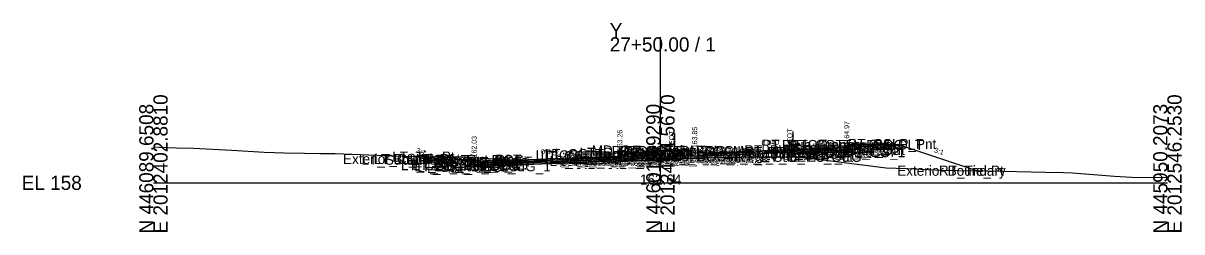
# Model space of a CAD drawing. Extents: x -26 to 3203, y -10 to 9532.
# Drawn here: x 1974.3 to 2202.8, y 1490.3 to 1531.6 of the extents above; entities that cross this region are included whole.
import ezdxf

# ---------------------------------------------------------------- set-up
doc = ezdxf.new("R2010")
doc.units = 0
for name, color, linetype in [('Default', 7, 'Continuous'), ('Exist CMT Pavement', 7, 'Continuous'), ('Exist Cross Section Cell', 7, 'Continuous'), ('Exist XS Center Line Elevation Label', 7, 'Continuous'), ('Exist XS Ground Line', 7, 'Continuous'), ('Prop CMT Conc Surface', 7, 'Continuous'), ('Prop CMT Concrete Structures', 7, 'Continuous'), ('Prop CMT Pvmt Course 1', 7, 'Continuous'), ('Prop CMT Pvmt Course 1 CG', 7, 'Continuous'), ('Prop CMT Pvmt Course 2', 7, 'Continuous'), ('Prop CMT Pvmt Course 2 Wedge', 7, 'Continuous'), ('Prop CMT Pvmt Course 3', 7, 'Continuous'), ('Prop CMT Pvmt Course 3 Wedge', 7, 'Continuous'), ('Prop CMT Pvmt Surface', 7, 'Continuous'), ('Prop CMT Slope Grass', 7, 'Continuous'), ('Prop CMT Subgrade Earthwork', 7, 'Continuous'), ('Prop XS Hydro Elevations', 7, 'Continuous'), ('Prop XS Label Text', 7, 'Continuous'), ('Prop XS SE Text', 7, 'Continuous'), ('Prop XS Side Slope Text', 7, 'Continuous'), ('Scratch_Level_0', 7, 'Continuous')]:
    doc.layers.add(name, color=color, linetype=linetype)

msp = doc.modelspace()

# ---------------------------------------------------------------- linework, layer by layer
at = {"layer": 'Exist CMT Pavement'}
msp.add_lwpolyline([(2102.78, 1504.77), (2103.59, 1504.79), (2107, 1504.91), (2108.77, 1504.94), (2110.58, 1504.98), (2114.05, 1505.06), (2114.58, 1505.07), (2115.66, 1505.09), (2117.71, 1505.12), (2119.3, 1505.13), (2121.31, 1505.15), (2122.86, 1505.15), (2124.45, 1505.16), (2124.95, 1505.16), (2126.14, 1505.16), (2126.14, 1505.16)], dxfattribs=at)
at = {"layer": 'Exist Cross Section Cell'}
for p, q in [((2100, 1500), (2100, 1528.76)), ((2000, 1500), (2100, 1500)), ((2100, 1500), (2200, 1500))]:
    msp.add_line(p, q, dxfattribs=at)
at = {"layer": 'Exist XS Ground Line'}
msp.add_lwpolyline([(2000, 1507.11), (2001.1, 1507.06), (2004.56, 1506.89), (2007.92, 1506.85), (2015.45, 1506.45), (2021.87, 1506.09), (2025.78, 1505.96), (2029.79, 1505.89), (2032.85, 1505.8), (2035.82, 1505.77), (2044.14, 1505.5), (2049.77, 1505.27), (2058.48, 1505.12), (2061.14, 1505.13), (2064.92, 1504.88), (2075.31, 1504.28), (2082.73, 1503.86), (2083.5, 1503.83), (2086.7, 1503.67), (2092.89, 1504.29), (2093.48, 1504.35), (2094.59, 1504.4), (2095.31, 1504.43), (2097.77, 1504.54), (2100, 1504.64), (2102.11, 1504.74), (2102.78, 1504.77), (2103.59, 1504.79), (2107, 1504.91), (2108.77, 1504.94), (2110.58, 1504.98), (2114.05, 1505.06), (2114.58, 1505.07), (2115.66, 1505.09), (2117.71, 1505.12), (2119.3, 1505.13), (2121.31, 1505.15), (2122.86, 1505.15), (2124.45, 1505.16), (2124.95, 1505.16), (2126.14, 1505.16), (2127.25, 1505.15), (2128.96, 1504.94), (2144.53, 1502.98), (2148.53, 1502.83), (2155.65, 1502.53), (2158.85, 1502.45), (2163.98, 1502.38), (2164.6, 1502.36), (2175.97, 1502.1), (2179.49, 1502.01), (2181.3, 1501.98), (2189.55, 1501.34), (2192.96, 1501.12), (2200, 1501.03)], dxfattribs=at)
at = {"layer": 'Prop CMT Conc Surface'}
for points in [[(2108.75, 1505.93), (2106.75, 1505.85), (2106.75, 1506.02), (2106, 1506.27)], [(2134.75, 1506.97), (2136.75, 1506.97)], [(2136.75, 1506.97), (2136.75, 1507.47), (2137.25, 1507.47)], [(2058.75, 1504.62), (2053.75, 1504.72)], [(2063.25, 1504.03), (2063.25, 1504.53), (2062.75, 1504.53)], [(2065.25, 1504.19), (2063.25, 1504.03)], [(2091.25, 1505.23), (2092, 1505.26), (2092, 1505.43), (2092.76, 1505.68)]]:
    msp.add_lwpolyline(points, dxfattribs=at)
at = {"layer": 'Prop CMT Concrete Structures'}
for points in [[(2108.75, 1505.93), (2106.75, 1505.85), (2106.75, 1506.02), (2106, 1506.27)], [(2106, 1506.27), (2106, 1505.24)], [(2134.75, 1506.97), (2136.75, 1506.97), (2136.75, 1507.47), (2137.25, 1507.47)], [(2137.25, 1507.47), (2137.25, 1506.49), (2134.75, 1506.39)], [(2134.75, 1506.39), (2134.75, 1506.97)], [(2145.75, 1507.65), (2137.75, 1507.49)], [(2137.75, 1507.49), (2137.75, 1507.16)], [(2137.75, 1507.16), (2145.75, 1507.32)], [(2145.75, 1507.32), (2145.75, 1507.65)], [(2053.75, 1504.39), (2053.75, 1504.72)], [(2053.75, 1504.72), (2058.75, 1504.62)], [(2058.75, 1504.29), (2053.75, 1504.39)], [(2058.75, 1504.62), (2058.75, 1504.29)], [(2065.25, 1504.19), (2063.25, 1504.03), (2063.25, 1504.53), (2062.75, 1504.53)], [(2062.75, 1504.53), (2062.75, 1503.51), (2065.25, 1503.61)], [(2065.25, 1503.61), (2065.25, 1504.19)], [(2091.25, 1505.23), (2092, 1505.26), (2092, 1505.43), (2092.76, 1505.68)], [(2091.25, 1504.65), (2091.25, 1505.23)], [(2092.76, 1504.71), (2091.25, 1504.65)], [(2092.76, 1505.68), (2092.76, 1504.71)], [(2106, 1505.24), (2108.75, 1505.35)], [(2108.75, 1505.35), (2108.75, 1505.93)]]:
    msp.add_lwpolyline(points, dxfattribs=at)
at = {"layer": 'Prop CMT Pvmt Course 1'}
for points in [[(2108.75, 1505.93), (2134.75, 1506.97)], [(2134.75, 1506.72), (2127.25, 1506.42), (2108.75, 1505.68)], [(2134.75, 1506.97), (2134.75, 1506.72)], [(2091.25, 1505.23), (2065.25, 1504.19)], [(2065.25, 1503.94), (2091.25, 1504.98)], [(2065.25, 1504.19), (2065.25, 1503.94)], [(2091.25, 1504.98), (2091.25, 1505.23)], [(2091.25, 1504.98), (2091.25, 1504.98), (2091.25, 1504.98)], [(2108.75, 1505.68), (2108.75, 1505.93)], [(2108.75, 1505.68), (2108.75, 1505.68)]]:
    msp.add_lwpolyline(points, dxfattribs=at)
at = {"layer": 'Prop CMT Pvmt Course 1 CG'}
for points in [[(2134.75, 1506.39), (2137.75, 1506.51), (2138.07, 1506.19)], [(2134.75, 1506.06), (2134.75, 1506.39)], [(2138.07, 1506.19), (2134.75, 1506.06)], [(2091.25, 1504.65), (2093.26, 1504.73), (2093.58, 1504.41)], [(2091.25, 1504.32), (2091.25, 1504.65)], [(2093.58, 1504.41), (2091.25, 1504.32)], [(2108.75, 1505.35), (2105.5, 1505.22), (2105.15, 1504.87)], [(2105.15, 1504.87), (2108.75, 1505.02)], [(2108.75, 1505.02), (2108.75, 1505.35)], [(2065.25, 1503.61), (2062.25, 1503.49), (2061.9, 1503.14)], [(2061.9, 1503.14), (2065.25, 1503.28)], [(2065.25, 1503.28), (2065.25, 1503.61)]]:
    msp.add_lwpolyline(points, dxfattribs=at)
at = {"layer": 'Prop CMT Pvmt Course 2'}
for points in [[(2126.14, 1506.38), (2134.75, 1506.72)], [(2134.75, 1506.39), (2126.14, 1506.05)], [(2126.14, 1506.05), (2126.14, 1506.38)], [(2134.75, 1506.72), (2134.75, 1506.39)], [(2091.25, 1504.98), (2065.25, 1503.94)], [(2065.25, 1503.61), (2091.25, 1504.65)], [(2065.25, 1503.94), (2065.25, 1503.61)], [(2091.25, 1504.65), (2091.25, 1504.98)], [(2108.75, 1505.68), (2108.75, 1505.68)]]:
    msp.add_lwpolyline(points, dxfattribs=at)
msp.add_lwpolyline([(2108.75, 1505.68), (2108.75, 1505.35), (2108.75, 1505.35)], close=True, dxfattribs=at)
at = {"layer": 'Prop CMT Pvmt Course 2 Wedge'}
msp.add_lwpolyline([(2108.75, 1505.68), (2126.14, 1506.38)], dxfattribs=at)
at = {"layer": 'Prop CMT Pvmt Course 3'}
for points in [[(2126.14, 1506.05), (2134.75, 1506.39)], [(2134.75, 1506.06), (2126.14, 1505.71)], [(2126.14, 1505.71), (2126.14, 1506.05)], [(2134.75, 1506.39), (2134.75, 1506.06)], [(2091.25, 1504.65), (2065.25, 1503.61)], [(2065.25, 1503.28), (2091.25, 1504.32)], [(2091.25, 1504.32), (2091.25, 1504.65)], [(2108.75, 1505.35), (2108.75, 1505.35), (2108.75, 1505.02), (2108.75, 1505.02)], [(2108.75, 1505.02), (2108.75, 1505.35)], [(2065.25, 1503.61), (2065.25, 1503.28)]]:
    msp.add_lwpolyline(points, dxfattribs=at)
at = {"layer": 'Prop CMT Pvmt Course 3 Wedge'}
msp.add_lwpolyline([(2108.75, 1505.35), (2126.14, 1506.05)], dxfattribs=at)
at = {"layer": 'Prop CMT Pvmt Surface'}
for points in [[(2108.75, 1505.93), (2134.75, 1506.97)], [(2091.25, 1505.23), (2065.25, 1504.19)]]:
    msp.add_lwpolyline(points, dxfattribs=at)
at = {"layer": 'Prop CMT Slope Grass'}
for points in [[(2092.76, 1505.68), (2099.38, 1506.4)], [(2106, 1506.27), (2099.38, 1506.4)], [(2137.25, 1507.47), (2146.75, 1507.66)], [(2146.75, 1507.66), (2162.55, 1502.4)], [(2053.25, 1504.72), (2051.71, 1505.24)], [(2062.75, 1504.53), (2053.25, 1504.72)]]:
    msp.add_lwpolyline(points, dxfattribs=at)
at = {"layer": 'Prop CMT Subgrade Earthwork'}
for points in [[(2103.71, 1506.32), (2105.15, 1504.87)], [(2126.14, 1505.71), (2134.75, 1506.06)], [(2134.75, 1506.06), (2138.07, 1506.19), (2139.4, 1507.52)], [(2134.75, 1506.06), (2134.75, 1506.06)], [(2065.25, 1503.28), (2061.9, 1503.14), (2060.47, 1504.58)], [(2091.25, 1504.32), (2065.25, 1503.28)], [(2093.58, 1504.41), (2091.25, 1504.32)], [(2091.25, 1504.32), (2091.25, 1504.32)], [(2091.25, 1504.32), (2091.25, 1504.32)], [(2095.11, 1505.94), (2093.58, 1504.41)], [(2105.15, 1504.87), (2108.75, 1505.02)], [(2108.75, 1505.02), (2108.74, 1504.94)], [(2108.75, 1505.02), (2108.75, 1505.02)], [(2108.75, 1505.02), (2108.75, 1505.02)], [(2126.14, 1505.71), (2126.15, 1505.16)], [(2065.25, 1503.28), (2065.25, 1503.28)]]:
    msp.add_lwpolyline(points, dxfattribs=at)
at = {"layer": 'Prop XS Label Text'}
for p, q in [((2102.78, 1509.77), (2102.78, 1504.77)), ((2126.14, 1510.16), (2126.14, 1505.16))]:
    msp.add_line(p, q, dxfattribs=at)

# ---------------------------------------------------------------- texts
at = {"layer": 'Default'}
msp.add_text('-', height=0.0001, dxfattribs=at).set_placement((2000, 1500))
at = {"layer": 'Exist Cross Section Cell'}
for s, p in [('Y', (2090, 1528.76)), ('27+50.00 / 1', (2090, 1525.96)), ('EL 158', (1974, 1498.6))]:
    msp.add_text(s, height=2.8, dxfattribs=at).set_placement(p)
for s, p in [('N 446089.6508', (2000, 1490)), ('E 2012402.8810', (2002.8, 1490)), ('N 446019.9290', (2100, 1490)), ('E 2012474.5670', (2102.8, 1490)), ('N 445950.2073', (2200, 1490)), ('E 2012546.2530', (2202.8, 1490))]:
    msp.add_text(s, height=2.8, rotation=90, dxfattribs=at).set_placement(p)
at = {"layer": 'Exist XS Center Line Elevation Label'}
msp.add_text('162.64', height=2, dxfattribs=at).set_placement((2095.96, 1499.64))
at = {"layer": 'Prop XS Hydro Elevations'}
for s, p in [('163.85', (2107.25, 1506.85)), ('164.97', (2137.25, 1507.97)), ('162.03', (2063.75, 1505.03)), ('163.26', (2092.5, 1506.26))]:
    msp.add_text(s, height=1, rotation=90, dxfattribs=at).set_placement(p)
at = {"layer": 'Prop XS Label Text'}
for p in [(2102.68, 1505.8), (2126.04, 1506.18)]:
    msp.add_text('E. EOT', height=1, rotation=90, dxfattribs=at).set_placement(p)
at = {"layer": 'Prop XS SE Text'}
for p in [(2119.96, 1507.38), (2076.46, 1505.64)]:
    msp.add_text('0.040', height=1, rotation=2.2906, dxfattribs=at).set_placement(p)
at = {"layer": 'Prop XS Side Slope Text'}
for p in [(2051.73, 1506.02), (2153.9, 1506.07)]:
    msp.add_text('3:1', height=1, rotation=341.5651, dxfattribs=at).set_placement(p)
at = {"layer": 'Scratch_Level_0'}
for s, p in [('RT_Sub_Trench_Out_DLT', (2119.92, 1506.52)), ('RT_CG_Top_Face', (2123.96, 1506.47)), ('RT_CG_Top_BOC', (2125.49, 1506.47)), ('RT_CSLP_Pnt', (2136.88, 1506.66)), ('LT_Tie_Pt', (2047.08, 1504.19)), ('LT_CG_Top_Face_Med', (2075.37, 1504.43)), ('LT_CG_Top_Gut_Med', (2076.35, 1504.26)), ('LT_CG_Top_BOC_Med', (2077.15, 1504.68)), ('LT_PV1_PGL', (2083.03, 1504.23)), ('LT_Sub_DLT_In', (2084.05, 1504.94)), ('MD_Crown Point', (2086.45, 1505.4)), ('RT_CG_Top_BOC_Med', (2090.35, 1505.27)), ('RT_CG_Bot BOC In', (2091.84, 1504.24)), ('RT_CG_Top_BOC In', (2091.97, 1505.27)), ('RT_Sub_DLT_In', (2092.61, 1505.32)), ('RT_CG_Top FOC In', (2092.61, 1505.02)), ('RT_CG_Top_Gut In', (2092.64, 1504.85)), ('RT_CG1_Shelf_In', (2093.63, 1504.22)), ('RT_CG_Bot_IE_Med', (2094.77, 1504.35)), ('RT_PV_Sub_Tie_In', (2095.25, 1503.94)), ('RT_Sub_IEOT_CG_1', (2095.57, 1504.02)), ('RT_Sub_IEEOP', (2098.56, 1504.02)), ('RT_PV2_IEEOP', (2098.66, 1504.68)), ('RT_PV3_IEEOP', (2098.66, 1504.35)), ('RT_Sub_PGL', (2099.82, 1504.02)), ('RT_PV2_PGL', (2099.92, 1504.68)), ('RT_PV3_PGL', (2099.92, 1504.35)), ('RT_PV1_PGL', (2100.48, 1504.93)), ('RT_PV_Sub_Tie_Out', (2112.16, 1504.15)), ('RT_PV_OEEOP_EG', (2114.74, 1504.15)), ('RT_Sub_OEEOP', (2116.41, 1504.76)), ('RT_PV2_OEEOP', (2116.51, 1505.42)), ('RT_PV3_OEEOP', (2116.51, 1505.09)), ('RT_Sub_OEOT_CG_1', (2120.92, 1505.06)), ('RT_CG1_Shelf_Out', (2124.25, 1505.51)), ('RT_CG_Bot_IE', (2124.62, 1505.39)), ('RT_Sub_OEOT', (2124.78, 1505.06)), ('RT_PV2_OEOT', (2124.88, 1505.72)), ('RT_PV3_OEOT', (2124.88, 1505.39)), ('RT_CG_Top_Gut', (2124.94, 1505.97)), ('RT_PV1_OEOT', (2125.44, 1505.97)), ('RT_CG_Bot_BOC', (2125.52, 1505.49)), ('RT_Sub_OEOP', (2128.13, 1505.19)), ('Exterior Boundary', (2037.39, 1503.72)), ('LT_Sub_Trench_Out_DLT', (2041.03, 1503.58)), ('LT_CSLP_Pnt', (2043.42, 1503.72)), ('LT_CG1_Shelf_Out', (2048.8, 1502.49)), ('LT_CG_Top_Face', (2050.51, 1503.53)), ('LT_CG_Top_BOC', (2051.03, 1503.53)), ('LT_CG_Bot_BOC', (2051.06, 1502.51)), ('LT_Sub_OEOT_CG_1', (2051.47, 1502.28)), ('LT_CG_Top_Gut', (2051.49, 1503.03)), ('LT_Sub_OEOP', (2052.01, 1502.14)), ('LT_CG_Bot_IE', (2055.16, 1502.61)), ('LT_Sub_OEOT', (2055.33, 1502.28)), ('LT_PV2_OEOT', (2055.42, 1502.94)), ('LT_PV3_OEOT', (2055.42, 1502.61)), ('LT_PV1_OEOT', (2055.99, 1503.19)), ('LT_CG_Bot_BOC_Med', (2077.19, 1503.71)), ('LT_CG_Bot_IE_Med', (2077.31, 1503.65)), ('LT_Sub_IEOT_CG_1', (2078.12, 1503.32)), ('LT_Sub_OEEOP', (2080.46, 1503.32)), ('LT_PV2_OEEOP', (2080.56, 1503.98)), ('LT_PV3_OEEOP', (2080.56, 1503.65)), ('LT_Sub_IEEOP', (2081.11, 1503.32)), ('LT_PV2_IEEOP', (2081.2, 1503.98)), ('LT_CG1_Shelf_In', (2081.43, 1503.73)), ('LT_Sub_PGL', (2082.37, 1503.32)), ('LT_PV2_PGL', (2082.46, 1503.98)), ('LT_Sub_IEOP', (2084.34, 1503.41)), ('RT_Sub_IEOP', (2095.86, 1503.87)), ('RT_PV_IEEOP_EG', (2096.89, 1503.94)), ('Exterior Boundary', (2146.69, 1501.4)), ('RT_Tie_Pt', (2154.94, 1501.4))]:
    msp.add_text(s, height=2, dxfattribs=at).set_placement(p)

doc.saveas('drawing.dxf')
